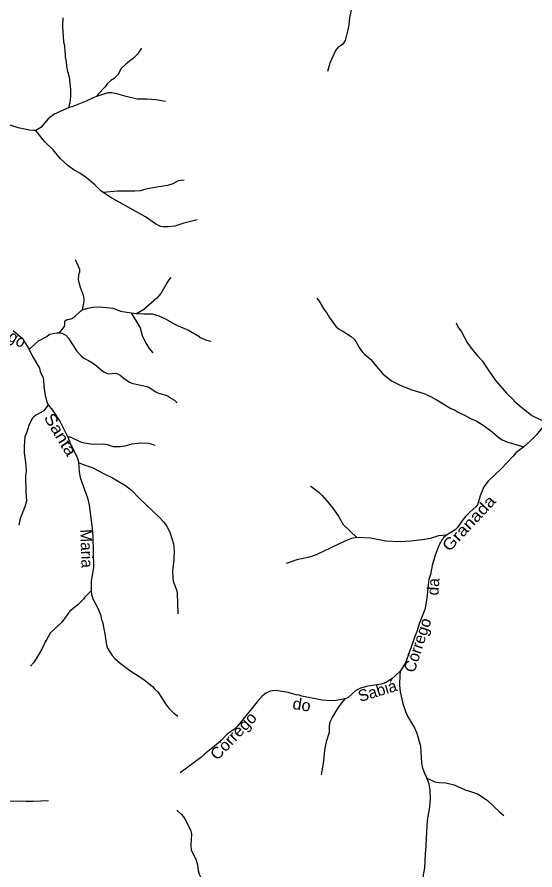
# Model space of a CAD drawing. Extents: x 551.6 to 577.6, y 7567 to 7594.7.
# Drawn here: x 557.32 to 561.8, y 7572.36 to 7579.74 of the extents above; entities that cross this region are included whole.
import ezdxf
from ezdxf.enums import TextEntityAlignment as Align

# ---------------------------------------------------------------- set-up
doc = ezdxf.new("R2010")
doc.units = 0
doc.header["$LTSCALE"] = 0.04
doc.layers.add('61', color=7, linetype='Continuous')
doc.layers.add('7', color=7, linetype='Continuous', lineweight=25)

msp = doc.modelspace()

# ---------------------------------------------------------------- linework, layer by layer
at = {"layer": '7'}
for points in [[(560.2151, 7579.8404), (560.191, 7579.731), (560.1861, 7579.6698), (560.1789, 7579.6247), (560.1556, 7579.5346), (560.1347, 7579.5032), (560.1153, 7579.4871), (560.0944, 7579.475), (560.0711, 7579.4461), (560.0228, 7579.3366), (560.0011, 7579.265)], [(557.7122, 7579.7302), (557.709, 7579.6569), (557.7114, 7579.6086), (557.7178, 7579.5233), (557.7251, 7579.4895), (557.7251, 7579.467), (557.7283, 7579.4557), (557.7315, 7579.3897), (557.7396, 7579.3511), (557.7428, 7579.3109), (557.7524, 7579.2658), (557.7669, 7579.2207), (557.7782, 7579.1113), (557.7782, 7579.0517), (557.7717, 7578.9954), (557.7613, 7578.9504)], [(558.3907, 7579.4678), (558.3576, 7579.4147), (558.3255, 7579.3825), (558.2579, 7579.3318), (558.2168, 7579.2915), (558.187, 7579.2376), (558.1556, 7579.2054), (558.1259, 7579.1877), (558.0937, 7579.1604), (558.0776, 7579.1338), (558.0148, 7579.0662), (558.0017, 7579.0482)], [(558.0017, 7579.0482), (557.973, 7579.0388), (557.9142, 7579.009), (557.7991, 7578.9632), (557.7613, 7578.9504)], [(558.5999, 7579.0058), (558.5146, 7579.0211), (558.4414, 7579.0259), (558.3544, 7579.0259), (558.2579, 7579.0485), (558.1774, 7579.0718), (558.1323, 7579.0799), (558.1001, 7579.0807), (558.0017, 7579.0482)], [(557.7613, 7578.9504), (557.635, 7578.8956), (557.5851, 7578.8561), (557.5215, 7578.7805), (557.4766, 7578.756)], [(557.4766, 7578.756), (557.457, 7578.7549), (557.4225, 7578.7587), (557.3243, 7578.7797), (557.2454, 7578.8046), (557.1666, 7578.8223), (557.1247, 7578.8207), (557.0957, 7578.828), (557.0571, 7578.8328), (557.0233, 7578.8312), (556.9782, 7578.8199), (556.9557, 7578.8207), (556.9404, 7578.8247), (556.8567, 7578.8698), (556.843, 7578.873), (556.8044, 7578.8722), (556.7609, 7578.8642)], [(557.8104, 7578.4111), (557.7533, 7578.4513), (557.6889, 7578.5133), (557.6277, 7578.5881), (557.5537, 7578.6614), (557.4766, 7578.756)], [(558.0616, 7578.2198), (558.0414, 7578.234), (557.989, 7578.2863), (557.915, 7578.3467), (557.8579, 7578.3853), (557.8104, 7578.4111)], [(558.7609, 7578.3258), (558.7094, 7578.3185), (558.6619, 7578.2928), (558.6184, 7578.2783), (558.5235, 7578.2662), (558.4301, 7578.2485), (558.3802, 7578.234), (558.3351, 7578.23), (558.1838, 7578.2308), (558.0616, 7578.2198)], [(558.8735, 7577.9813), (558.7585, 7577.9531), (558.6812, 7577.9282), (558.6249, 7577.9218), (558.5798, 7577.9218), (558.5573, 7577.925), (558.5122, 7577.9475), (558.4253, 7578.0079), (558.1211, 7578.1777), (558.0616, 7578.2198)], [(557.8168, 7577.6393), (557.8554, 7577.5556), (557.8554, 7577.5306), (557.8466, 7577.5065), (557.8426, 7577.4646), (557.8603, 7577.3987), (557.886, 7577.3311), (557.8925, 7577.2972), (557.8933, 7577.2747), (557.8796, 7577.2036)], [(558.6466, 7577.4832), (558.6289, 7577.4646), (558.6128, 7577.4405), (558.5597, 7577.3439), (558.525, 7577.3045), (558.4124, 7577.2063), (558.3697, 7577.1821), (558.3475, 7577.1732)], [(559.9101, 7577.3045), (559.9286, 7577.2795), (559.9761, 7577.2007), (559.993, 7577.1797), (560.0155, 7577.1395), (560.0759, 7577.0574), (560.1033, 7577.0357), (560.133, 7577.0204), (560.2063, 7576.9729), (560.232, 7576.9496), (560.2481, 7576.9287), (560.2763, 7576.8779), (560.3028, 7576.8409), (560.3254, 7576.8176), (560.3753, 7576.7757), (560.4244, 7576.713), (560.4807, 7576.6494), (560.5548, 7576.5906), (560.6352, 7576.5504)], [(557.6818, 7577.0053), (557.7251, 7577.0606), (557.7299, 7577.0767), (557.7299, 7577.1049), (557.7347, 7577.1121), (557.7492, 7577.1218), (557.7718, 7577.1234), (557.7903, 7577.1298), (557.8144, 7577.1451), (557.8627, 7577.1934), (557.8796, 7577.2036)], [(557.8796, 7577.2036), (557.9263, 7577.2192), (557.9697, 7577.2264), (558.0277, 7577.2312), (558.1468, 7577.2184), (558.2112, 7577.1934), (558.302, 7577.1768), (558.3475, 7577.1732), (558.4124, 7577.1701)], [(558.302, 7577.1768), (558.3794, 7577.0494), (558.3987, 7576.9818), (558.4261, 7576.9222), (558.4582, 7576.8691), (558.4904, 7576.8313)], [(558.4124, 7577.1701), (558.4848, 7577.1693), (558.5412, 7577.1516), (558.5991, 7577.1258), (558.6941, 7577.0711), (558.7979, 7577.0284), (558.8872, 7576.9753), (558.8936, 7576.9689), (558.9548, 7576.9423), (558.9943, 7576.9319)], [(561.1141, 7577.092), (561.1294, 7577.0574), (561.1608, 7577.0124), (561.2099, 7576.9222), (561.2348, 7576.8836), (561.296, 7576.8103), (561.3443, 7576.7596), (561.3909, 7576.684), (561.4561, 7576.5914), (561.5511, 7576.4828), (561.6138, 7576.4216), (561.6138, 7576.4176), (561.6646, 7576.3725), (561.77, 7576.2912), (561.8473, 7576.2526), (561.908, 7576.2318)], [(557.2811, 7577.024), (557.3581, 7576.9584), (557.4166, 7576.8677)], [(557.4166, 7576.8677), (557.4295, 7576.871), (557.5005, 7576.9351), (557.5722, 7576.9745), (557.5963, 7576.9922), (557.6591, 7577.0043), (557.6818, 7577.0053)], [(557.6818, 7577.0053), (557.7025, 7577.0035), (557.7379, 7576.985), (557.7613, 7576.96), (557.8289, 7576.8498), (557.8699, 7576.8055), (557.8925, 7576.7862), (557.9335, 7576.7661), (557.9673, 7576.7451), (558.0027, 7576.7194), (558.0454, 7576.6808), (558.0663, 7576.6679), (558.0889, 7576.6566), (558.1098, 7576.6518), (558.1677, 7576.655), (558.187, 7576.651), (558.2064, 7576.6397), (558.2385, 7576.6124), (558.2868, 7576.5793), (558.3078, 7576.5705)], [(557.4166, 7576.8677), (557.4466, 7576.8063), (557.5086, 7576.7001), (557.5158, 7576.6711), (557.5392, 7576.6212), (557.5432, 7576.5987), (557.5455, 7576.541), (557.5589, 7576.4629), (557.5723, 7576.4071), (557.5849, 7576.3825)], [(558.3078, 7576.5705), (558.451, 7576.5375), (558.5154, 7576.494), (558.5395, 7576.4828), (558.5926, 7576.4675), (558.6289, 7576.453), (558.6313, 7576.449), (558.6764, 7576.4216), (558.6997, 7576.3999)], [(560.6352, 7576.5504), (560.7318, 7576.5117), (560.7801, 7576.4989), (560.8429, 7576.4763), (560.8815, 7576.461), (560.9427, 7576.4297), (561.069, 7576.3508), (561.1004, 7576.3379), (561.1374, 7576.3154), (561.1938, 7576.2896), (561.2388, 7576.2639), (561.2871, 7576.2429), (561.3386, 7576.2124), (561.4135, 7576.1592), (561.4851, 7576.0989)], [(557.5849, 7576.3825), (557.5456, 7576.3307), (557.4772, 7576.2928), (557.4595, 7576.2792), (557.4466, 7576.2631), (557.416, 7576.2043), (557.4032, 7576.1544), (557.3838, 7576.1061), (557.3758, 7576.0224), (557.3758, 7575.9661), (557.3871, 7575.8872), (557.3935, 7575.8116), (557.3887, 7575.7633), (557.3903, 7575.6297)], [(557.5849, 7576.3825), (557.6221, 7576.3363), (557.6888, 7576.2349), (557.7556, 7576.1029)], [(561.908, 7576.2318), (561.8835, 7576.2116), (561.8086, 7576.1198), (561.7595, 7576.0699), (561.6995, 7576.0188)], [(557.7556, 7576.1029), (557.7774, 7576.0434), (557.8249, 7575.9516), (557.841, 7575.9114), (557.8473, 7575.8834)], [(558.5106, 7576.0297), (558.4768, 7576.0434), (558.4542, 7576.049), (558.3866, 7576.0506), (558.3078, 7576.0409), (558.2482, 7576.024), (558.2064, 7576.0176), (558.1484, 7576.0176), (558.0969, 7576.0353), (558.0631, 7576.0434), (557.973, 7576.0401), (557.9118, 7576.0466), (557.8732, 7576.0578), (557.7766, 7576.1013), (557.7556, 7576.1029)], [(561.4851, 7576.0989), (561.5133, 7576.0804), (561.5543, 7576.0619), (561.6995, 7576.0188)], [(561.6995, 7576.0188), (561.6308, 7575.9677), (561.6066, 7575.9363), (561.5076, 7575.8309), (561.3909, 7575.7231), (561.3555, 7575.6716)], [(557.8473, 7575.8834), (557.8522, 7575.8019), (557.8619, 7575.7536), (557.9247, 7575.5782), (557.9391, 7575.5138), (557.9665, 7575.3158)], [(557.8473, 7575.8834), (557.886, 7575.8663), (557.9649, 7575.8414), (558.0792, 7575.781), (558.142, 7575.752), (558.253, 7575.6844), (558.3045, 7575.6434), (558.3713, 7575.5758), (558.546, 7575.4108), (558.583, 7575.3706), (558.612, 7575.3319), (558.6409, 7575.2708), (558.6675, 7575.1806), (558.6715, 7575.1581), (558.6747, 7575.105), (558.6723, 7575.0663)], [(559.8522, 7575.678), (559.8675, 7575.6699), (559.9302, 7575.6233), (559.956, 7575.5983), (559.997, 7575.5532), (560.0485, 7575.4889), (560.1008, 7575.414), (560.1379, 7575.3464), (560.2557, 7575.2342), (560.2573, 7575.2326)], [(561.3555, 7575.6716), (561.3233, 7575.5943), (561.2984, 7575.517), (561.2855, 7575.5001), (561.2332, 7575.455), (561.1954, 7575.4156), (561.1632, 7575.377), (561.1278, 7575.3215), (561.1076, 7575.3005), (561.0311, 7575.254)], [(557.3903, 7575.6297), (557.3975, 7575.5524), (557.3822, 7575.4993), (557.342, 7575.3995), (557.3291, 7575.3424)], [(557.9665, 7575.3158), (557.9713, 7575.2434), (557.9778, 7574.9794), (557.9577, 7574.8539), (557.9555, 7574.772)], [(560.1516, 7575.2039), (559.9029, 7575.084), (559.8449, 7575.0647), (559.7355, 7575.0406), (559.6445, 7575.0108)], [(560.2557, 7575.2342), (560.2103, 7575.2273), (560.1516, 7575.2039)], [(561.0311, 7575.254), (560.962, 7575.2482), (560.8912, 7575.2257), (560.8429, 7575.2168), (560.7238, 7575.2023), (560.6304, 7575.1975), (560.5065, 7575.2031), (560.3729, 7575.2289), (560.2557, 7575.2342)], [(561.0311, 7575.254), (561.0055, 7575.2337), (561.0038, 7575.2265), (560.9942, 7575.2176), (560.9692, 7575.171), (560.9346, 7575.0824), (560.9072, 7574.9939), (560.8928, 7574.915), (560.8799, 7574.87), (560.8718, 7574.8249), (560.8638, 7574.7348), (560.8525, 7574.6559)], [(558.6723, 7575.0663), (558.6723, 7575.0374), (558.6611, 7574.9488), (558.6619, 7574.8812), (558.6683, 7574.849), (558.6949, 7574.7814), (558.6997, 7574.7525), (558.7053, 7574.5746)], [(557.9555, 7574.772), (557.8973, 7574.7155), (557.8892, 7574.7026), (557.841, 7574.651), (557.7717, 7574.5979), (557.7033, 7574.503), (557.6027, 7574.4064), (557.5641, 7574.338), (557.5641, 7574.3428), (557.5319, 7574.2744), (557.4796, 7574.1843), (557.4579, 7574.1505), (557.4313, 7574.1207)], [(557.9555, 7574.772), (557.9593, 7574.7444), (557.9713, 7574.7042), (558.0132, 7574.6237), (558.0341, 7574.5754), (558.0406, 7574.5593), (558.047, 7574.5223), (558.0534, 7574.5046)], [(560.8525, 7574.6559), (560.8429, 7574.6108), (560.7946, 7574.4869), (560.7753, 7574.4225), (560.7559, 7574.3774), (560.7238, 7574.2776), (560.7109, 7574.2487), (560.6795, 7574.1553), (560.633, 7574.0814)], [(558.0534, 7574.5046), (558.0744, 7574.4), (558.088, 7574.3034), (558.0969, 7574.2776), (558.1371, 7574.2132), (558.1605, 7574.1867), (558.2064, 7574.1472), (558.2917, 7574.0837), (558.4108, 7574.0056), (558.4872, 7573.9469), (558.5057, 7573.9251), (558.5339, 7573.8994), (558.5701, 7573.843)], [(560.633, 7574.0814), (560.587, 7574.037), (560.5572, 7574.0128), (560.5033, 7573.9774), (560.4662, 7573.9662), (560.4276, 7573.9589), (560.3503, 7573.9501), (560.286, 7573.9316), (560.2457, 7573.9106), (560.1821, 7573.8543), (560.162, 7573.8414), (560.1522, 7573.8385)], [(560.633, 7574.0814), (560.6272, 7574.0539), (560.6256, 7573.9557), (560.6304, 7573.8994), (560.6521, 7573.798), (560.6755, 7573.7288), (560.6932, 7573.6885), (560.7543, 7573.5871)], [(559.7805, 7573.8623), (559.7483, 7573.8728), (559.7403, 7573.872), (559.6614, 7573.8929), (559.5568, 7573.9114), (559.5246, 7573.9098), (559.5085, 7573.9058), (559.4683, 7573.8873), (559.4393, 7573.8648), (559.3902, 7573.8109), (559.2244, 7573.6056), (559.1955, 7573.5782), (559.1351, 7573.5356), (559.0747, 7573.4728), (559.024, 7573.4294)], [(558.5701, 7573.843), (558.5991, 7573.7948), (558.6256, 7573.7601), (558.6675, 7573.7175), (558.7061, 7573.6893)], [(560.1522, 7573.8385), (560.0767, 7573.8237), (560.0284, 7573.8221), (559.9544, 7573.8285), (559.7805, 7573.8623)], [(560.1522, 7573.8385), (560.0968, 7573.7706), (560.0445, 7573.6837), (560.022, 7573.6386), (560.0155, 7573.6048), (560.0155, 7573.5485), (559.9898, 7573.4664), (559.9809, 7573.4278), (559.9753, 7573.3956), (559.9681, 7573.299), (559.9463, 7573.1807)], [(560.7543, 7573.5871), (560.7737, 7573.5421), (560.8075, 7573.431), (560.8155, 7573.2845), (560.8219, 7573.2523), (560.8372, 7573.2024), (560.8605, 7573.1529)], [(559.024, 7573.4294), (558.9371, 7573.3618), (558.9033, 7573.328), (558.7255, 7573.2)], [(560.8605, 7573.1529), (560.8783, 7573.1042), (560.8879, 7573.0479), (560.8895, 7572.969), (560.8831, 7572.9127), (560.8847, 7572.903), (560.8662, 7572.8065), (560.8606, 7572.7501), (560.859, 7572.668), (560.8557, 7572.6487), (560.8533, 7572.565), (560.8477, 7572.4974)], [(560.8605, 7573.1529), (560.9298, 7573.1219), (560.9684, 7573.1155), (561.0264, 7573.1123), (561.0972, 7573.0962), (561.1922, 7573.0511), (561.2211, 7573.0447), (561.2984, 7573.0173), (561.3837, 7572.9634), (561.4899, 7572.862), (561.5262, 7572.8314)], [(557.5859, 7572.9562), (557.4531, 7572.9497), (557.3919, 7572.9497), (557.3501, 7572.9553), (557.2551, 7572.9497), (557.1537, 7572.9497), (556.9557, 7572.9577), (556.8285, 7572.9835), (556.7593, 7573.0068), (556.6265, 7573.0412)], [(558.6981, 7572.8757), (558.7359, 7572.8419), (558.756, 7572.8177), (558.7713, 7572.7952), (558.8164, 7572.7067), (558.8236, 7572.668), (558.8196, 7572.5763), (558.8228, 7572.5312), (558.8614, 7572.4524), (558.8759, 7572.4025), (558.8824, 7572.3542), (558.892, 7572.3236), (558.9057, 7572.2946), (558.9291, 7572.2721), (558.987, 7572.2511), (559.0135, 7572.2326), (559.0393, 7572.198), (559.0482, 7572.1755), (559.0675, 7572.0789), (559.0739, 7571.9904), (559.0691, 7571.9131)], [(560.8477, 7572.4974), (560.8396, 7572.3735), (560.8284, 7572.3171), (560.8236, 7572.2367), (560.8163, 7572.198), (560.8147, 7572.1691), (560.8211, 7572.1208), (560.8622, 7572.0057)]]:
    msp.add_lwpolyline(points, dxfattribs=at)

# ---------------------------------------------------------------- texts
at = {"layer": '61'}
for s, rotation, p in [('Córrego', 329.44, (557.1475, 7576.9939)), ('Maria', 271.969, (557.8675, 7575.1376)), ('da', 86.103, (560.9657, 7574.8058)), ('Córrego', 72, (560.828, 7574.2887)), ('Sabiá', 16.838, (560.4479, 7573.8607))]:
    msp.add_text(s, height=0.1, rotation=rotation, dxfattribs=at).set_placement(p, align=Align.CENTER)
for s, rotation, width, p in [('Santa', 301.107, 1.15, (557.6475, 7576.0999)), ('Granada', 46.85, 1.15, (561.2609, 7575.3246)), ('do', 350.972, 1.05, (559.7708, 7573.7401)), ('Córrego', 46.336, 1.05, (559.2227, 7573.4843))]:
    msp.add_text(s, height=0.1, rotation=rotation, dxfattribs=dict(at, width=width)).set_placement(p, align=Align.CENTER)

doc.saveas('drawing.dxf')
